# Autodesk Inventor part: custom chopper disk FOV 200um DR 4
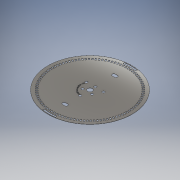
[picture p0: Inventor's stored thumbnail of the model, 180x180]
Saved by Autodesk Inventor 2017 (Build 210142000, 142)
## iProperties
Created: 2016-09
Part Number: custom chopper disk FOV 200um DR 4
Material: Generic
Document SubType Name: Modeling
Designer: Radek
Density: 1 g/cm^3
Appearance: Mirror
Author: Radek
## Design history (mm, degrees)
workplane "Work Plane1"
sketch "Sketch1"
  geometry: L1 (-46.781, 4.422)-(-44.253, 4.183) reference; L2 (-44.362, 2.791)-(-46.897, 2.951) reference; L3 (-46.411, 7.351)-(-43.903, 6.954) reference; L4 (-44.099, 5.571)-(-46.619, 5.889) reference; L5 (-45.858, 10.251)-(-43.38, 9.696) reference; L6 (-43.663, 8.329)-(-46.158, 8.805) reference; L7 (-45.124, 13.11)-(-42.685, 12.401) reference; L8 (-43.054, 11.054)-(-45.514, 11.686) reference; L9 (-44.212, 15.917)-(-41.822, 15.057) reference; L10 (-42.274, 13.736)-(-44.69, 14.521) reference; L11 (-43.125, 18.662)-(-40.794, 17.653) reference; L12 (-41.329, 16.363)-(-43.69, 17.298) reference; L13 (-41.868, 21.333)-(-39.605, 20.18) reference; L14 (-40.22, 18.926)-(-42.518, 20.007) reference; L15 (-40.446, 23.92)-(-38.26, 22.627) reference; L16 (-38.952, 21.414)-(-41.178, 22.638) reference; L17 (-38.865, 26.412)-(-36.764, 24.985) reference; L18 (-37.53, 23.818)-(-39.675, 25.179) reference; L19 (-37.129, 28.801)-(-35.122, 27.244) reference; L20 (-35.961, 26.127)-(-38.016, 27.62) reference; L21 (-35.248, 31.075)-(-33.342, 29.395) reference; L22 (-34.249, 28.333)-(-36.206, 29.953) reference; L23 (-33.227, 33.227)-(-31.431, 31.431) reference; L24 (-32.403, 30.428)-(-34.254, 32.167) reference; L25 (-31.075, 35.248)-(-29.395, 33.342) reference; L26 (-30.428, 32.403)-(-32.167, 34.254) reference; L27 (-28.801, 37.129)-(-27.244, 35.122) reference; L28 (-28.333, 34.249)-(-29.953, 36.206) reference; L29 (-26.412, 38.865)-(-24.985, 36.764) reference; L30 (-26.127, 35.961)-(-27.62, 38.016) reference; L31 (-23.92, 40.446)-(-22.627, 38.26) reference; L32 (-23.818, 37.53)-(-25.179, 39.675) reference; L33 (-21.333, 41.868)-(-20.18, 39.605) reference; L34 (-21.414, 38.952)-(-22.638, 41.178) reference; L35 (-18.662, 43.125)-(-17.653, 40.794) reference; L36 (-18.926, 40.22)-(-20.007, 42.518) reference; L37 (-15.917, 44.212)-(-15.057, 41.822) reference; L38 (-16.363, 41.329)-(-17.298, 43.69) reference; L39 (-13.11, 45.124)-(-12.401, 42.685) reference; L40 (-13.736, 42.274)-(-14.521, 44.69) reference; L41 (-10.251, 45.858)-(-9.696, 43.38) reference; L42 (-11.054, 43.054)-(-11.686, 45.514) reference; L43 (-7.351, 46.411)-(-6.954, 43.903) reference; L44 (-8.329, 43.663)-(-8.805, 46.158) reference; L45 (-4.422, 46.781)-(-4.183, 44.253) reference; L46 (-5.571, 44.099)-(-5.889, 46.619) reference; L47 (-1.476, 46.967)-(-1.396, 44.428) reference; L48 (-2.791, 44.362)-(-2.951, 46.897) reference; L49 (1.476, 46.967)-(1.396, 44.428) reference; L50 (0, 44.45)-(0, 46.99) reference; L51 (4.422, 46.781)-(4.183, 44.253) reference; L52 (2.791, 44.362)-(2.951, 46.897) reference; L53 (7.351, 46.411)-(6.954, 43.903) reference; L54 (5.571, 44.099)-(5.889, 46.619) reference; L55 (10.251, 45.858)-(9.696, 43.38) reference; L56 (8.329, 43.663)-(8.805, 46.158) reference; L57 (13.11, 45.124)-(12.401, 42.685) reference; L58 (11.054, 43.054)-(11.686, 45.514) reference; L59 (15.917, 44.212)-(15.057, 41.822) reference; L60 (13.736, 42.274)-(14.521, 44.69) reference; L61 (18.662, 43.125)-(17.653, 40.794) reference; L62 (16.363, 41.329)-(17.298, 43.69) reference; L63 (21.333, 41.868)-(20.18, 39.605) reference; L64 (18.926, 40.22)-(20.007, 42.518) reference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; C1 r 50.8 at (0, 0) reference; C2 r 2.984 at (0, 0) reference; C3 r 1.524 at (0, 6.553) reference; C4 r 1.524 at (10.339, 5.969) reference; C5 r 2.984 at (0, 0) reference; C6 r 1.524 at (0, -11.938) reference; C7 r 1.524 at (-5.675, -3.277) reference; C8 r 1.524 at (-10.339, 5.969) reference; C9 r 1.524 at (5.675, -3.277) reference; C10 r 50.8 at (0, 0) reference; C11 r 1.524 at (-5.675, -3.277) reference; C12 r 1.524 at (-10.339, 5.969) reference; C13 r 1.524 at (0, 6.553) reference; C14 r 1.524 at (10.339, 5.969) reference; C15 r 1.524 at (5.675, -3.277) reference; C16 r 1.524 at (0, -11.938) reference; C17 r 2.984 at (0, 0) reference; A1 r 17.081 centre (0, 0) between (0, -17.081) and (17.081, 0) reference; A2 r 17.081 centre (0, 0) between (0, 17.081) and (-17.081, 0) reference; A3 r 43.18 centre (0, 0) between (0, 43.18) and (-43.18, 0) reference; A4 r 43.18 centre (0, 0) between (0, -43.18) and (43.18, 0) reference; A5 r 44.45 centre (0, 0) between (-44.253, 4.183) and (-44.362, 2.791) reference; A6 r 46.99 centre (0, 0) between (-46.781, 4.422) and (-46.897, 2.951) reference; A7 r 44.45 centre (0, 0) between (-43.903, 6.954) and (-44.099, 5.571) reference; A8 r 46.99 centre (0, 0) between (-46.411, 7.351) and (-46.619, 5.889) reference; A9 r 44.45 centre (0, 0) between (-43.38, 9.696) and (-43.663, 8.329) reference; A10 r 46.99 centre (0, 0) between (-45.858, 10.251) and (-46.158, 8.805) reference; A11 r 44.45 centre (0, 0) between (-42.685, 12.401) and (-43.054, 11.054) reference; A12 r 46.99 centre (0, 0) between (-45.124, 13.11) and (-45.514, 11.686) reference; A13 r 44.45 centre (0, 0) between (-41.822, 15.057) and (-42.274, 13.736) reference; A14 r 46.99 centre (0, 0) between (-44.212, 15.917) and (-44.69, 14.521) reference; A15 r 44.45 centre (0, 0) between (-40.794, 17.653) and (-41.329, 16.363) reference; A16 r 46.99 centre (0, 0) between (-43.125, 18.662) and (-43.69, 17.298) reference; A17 r 44.45 centre (0, 0) between (-39.605, 20.18) and (-40.22, 18.926) reference; A18 r 46.99 centre (0, 0) between (-41.868, 21.333) and (-42.518, 20.007) reference; A19 r 44.45 centre (0, 0) between (-38.26, 22.627) and (-38.952, 21.414) reference; A20 r 46.99 centre (0, 0) between (-40.446, 23.92) and (-41.178, 22.638) reference; A21 r 44.45 centre (0, 0) between (-36.764, 24.985) and (-37.53, 23.818) reference; A22 r 46.99 centre (0, 0) between (-38.865, 26.412) and (-39.675, 25.179) reference; A23 r 44.45 centre (0, 0) between (-35.122, 27.244) and (-35.961, 26.127) reference; A24 r 46.99 centre (0, 0) between (-37.129, 28.801) and (-38.016, 27.62) reference; A25 r 44.45 centre (0, 0) between (-33.342, 29.395) and (-34.249, 28.333) reference; A26 r 46.99 centre (0, 0) between (-35.248, 31.075) and (-36.206, 29.953) reference; A27 r 44.45 centre (0, 0) between (-31.431, 31.431) and (-32.403, 30.428) reference; A28 r 46.99 centre (0, 0) between (-33.227, 33.227) and (-34.254, 32.167) reference; A29 r 44.45 centre (0, 0) between (-29.395, 33.342) and (-30.428, 32.403) reference; A30 r 46.99 centre (0, 0) between (-31.075, 35.248) and (-32.167, 34.254) reference; A31 r 44.45 centre (0, 0) between (-27.244, 35.122) and (-28.333, 34.249) reference; A32 r 46.99 centre (0, 0) between (-28.801, 37.129) and (-29.953, 36.206) reference; A33 r 44.45 centre (0, 0) between (-24.985, 36.764) and (-26.127, 35.961) reference; A34 r 46.99 centre (0, 0) between (-26.412, 38.865) and (-27.62, 38.016) reference; A35 r 44.45 centre (0, 0) between (-22.627, 38.26) and (-23.818, 37.53) reference; A36 r 46.99 centre (0, 0) between (-23.92, 40.446) and (-25.179, 39.675) reference; A37 r 44.45 centre (0, 0) between (-20.18, 39.605) and (-21.414, 38.952) reference; A38 r 46.99 centre (0, 0) between (-21.333, 41.868) and (-22.638, 41.178) reference; A39 r 44.45 centre (0, 0) between (-17.653, 40.794) and (-18.926, 40.22) reference; A40 r 46.99 centre (0, 0) between (-18.662, 43.125) and (-20.007, 42.518) reference; A41 r 44.45 centre (0, 0) between (-15.057, 41.822) and (-16.363, 41.329) reference; A42 r 46.99 centre (0, 0) between (-15.917, 44.212) and (-17.298, 43.69) reference; A43 r 44.45 centre (0, 0) between (-12.401, 42.685) and (-13.736, 42.274) reference; A44 r 46.99 centre (0, 0) between (-13.11, 45.124) and (-14.521, 44.69) reference; A45 r 44.45 centre (0, 0) between (-9.696, 43.38) and (-11.054, 43.054) reference; A46 r 46.99 centre (0, 0) between (-10.251, 45.858) and (-11.686, 45.514) reference; A47 r 44.45 centre (0, 0) between (-6.954, 43.903) and (-8.329, 43.663) reference; A48 r 46.99 centre (0, 0) between (-7.351, 46.411) and (-8.805, 46.158) reference; A49 r 44.45 centre (0, 0) between (-4.183, 44.253) and (-5.571, 44.099) reference; A50 r 46.99 centre (0, 0) between (-4.422, 46.781) and (-5.889, 46.619) reference; A51 r 44.45 centre (0, 0) between (-1.396, 44.428) and (-2.791, 44.362) reference; A52 r 46.99 centre (0, 0) between (-1.476, 46.967) and (-2.951, 46.897) reference; A53 r 44.45 centre (0, 0) between (1.396, 44.428) and (0, 44.45) reference; A54 r 46.99 centre (0, 0) between (1.476, 46.967) and (0, 46.99) reference; A55 r 44.45 centre (0, 0) between (4.183, 44.253) and (2.791, 44.362) reference; A56 r 46.99 centre (0, 0) between (4.422, 46.781) and (2.951, 46.897) reference; A57 r 44.45 centre (0, 0) between (6.954, 43.903) and (5.571, 44.099) reference; A58 r 46.99 centre (0, 0) between (7.351, 46.411) and (5.889, 46.619) reference; A59 r 44.45 centre (0, 0) between (9.696, 43.38) and (8.329, 43.663) reference; A60 r 46.99 centre (0, 0) between (10.251, 45.858) and (8.805, 46.158) reference; A61 r 44.45 centre (0, 0) between (12.401, 42.685) and (11.054, 43.054) reference; A62 r 46.99 centre (0, 0) between (13.11, 45.124) and (11.686, 45.514) reference; A63 r 44.45 centre (0, 0) between (15.057, 41.822) and (13.736, 42.274) reference; A64 r 46.99 centre (0, 0) between (15.917, 44.212) and (14.521, 44.69) reference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; 1 further point
  constraints: 8 end point, 2 collinear, 1 parallel
extrude "Extrusion2" new body sketch "Sketch1" distance "d2" = 0.254; taper "d3" = 0 deg
sketch "Sketch2"
  geometry: L1 (-46.781, 4.422)-(-44.253, 4.183) reference; L2 (-44.362, 2.791)-(-46.897, 2.951) reference; L3 (-46.411, 7.351)-(-43.903, 6.954) reference; L4 (-44.099, 5.571)-(-46.619, 5.889) reference; L5 (-45.858, 10.251)-(-43.38, 9.696) reference; L6 (-43.663, 8.329)-(-46.158, 8.805) reference; L7 (-45.124, 13.11)-(-42.685, 12.401) reference; L8 (-43.054, 11.054)-(-45.514, 11.686) reference; L9 (-44.212, 15.917)-(-41.822, 15.057) reference; L10 (-42.274, 13.736)-(-44.69, 14.521) reference; L11 (-43.125, 18.662)-(-40.794, 17.653) reference; L12 (-41.329, 16.363)-(-43.69, 17.298) reference; L13 (-41.868, 21.333)-(-39.605, 20.18) reference; L14 (-40.22, 18.926)-(-42.518, 20.007) reference; L15 (-40.446, 23.92)-(-38.26, 22.627) reference; L16 (-38.952, 21.414)-(-41.178, 22.638) reference; L17 (-38.865, 26.412)-(-36.764, 24.985) reference; L18 (-37.53, 23.818)-(-39.675, 25.179) reference; L19 (-37.129, 28.801)-(-35.122, 27.244) reference; L20 (-35.961, 26.127)-(-38.016, 27.62) reference; L21 (-35.248, 31.075)-(-33.342, 29.395) reference; L22 (-34.249, 28.333)-(-36.206, 29.953) reference; L23 (-33.227, 33.227)-(-31.431, 31.431) reference; L24 (-32.403, 30.428)-(-34.254, 32.167) reference; L25 (-31.075, 35.248)-(-29.395, 33.342) reference; L26 (-30.428, 32.403)-(-32.167, 34.254) reference; L27 (-28.801, 37.129)-(-27.244, 35.122) reference; L28 (-28.333, 34.249)-(-29.953, 36.206) reference; L29 (-26.412, 38.865)-(-24.985, 36.764) reference; L30 (-26.127, 35.961)-(-27.62, 38.016) reference; L31 (-23.92, 40.446)-(-22.627, 38.26) reference; L32 (-23.818, 37.53)-(-25.179, 39.675) reference; L33 (-21.333, 41.868)-(-20.18, 39.605) reference; L34 (-21.414, 38.952)-(-22.638, 41.178) reference; L35 (-18.662, 43.125)-(-17.653, 40.794) reference; L36 (-18.926, 40.22)-(-20.007, 42.518) reference; L37 (-15.917, 44.212)-(-15.057, 41.822) reference; L38 (-16.363, 41.329)-(-17.298, 43.69) reference; L39 (-13.11, 45.124)-(-12.401, 42.685) reference; L40 (-13.736, 42.274)-(-14.521, 44.69) reference; L41 (-10.251, 45.858)-(-9.696, 43.38) reference; L42 (-11.054, 43.054)-(-11.686, 45.514) reference; L43 (-7.351, 46.411)-(-6.954, 43.903) reference; L44 (-8.329, 43.663)-(-8.805, 46.158) reference; L45 (-4.422, 46.781)-(-4.183, 44.253) reference; L46 (-5.571, 44.099)-(-5.889, 46.619) reference; L47 (-1.476, 46.967)-(-1.396, 44.428) reference; L48 (-2.791, 44.362)-(-2.951, 46.897) reference; L49 (1.476, 46.967)-(1.396, 44.428) reference; L50 (0, 44.45)-(0, 46.99) reference; L51 (4.422, 46.781)-(4.183, 44.253) reference; L52 (2.791, 44.362)-(2.951, 46.897) reference; L53 (7.351, 46.411)-(6.954, 43.903) reference; L54 (5.571, 44.099)-(5.889, 46.619) reference; L55 (10.251, 45.858)-(9.696, 43.38) reference; L56 (8.329, 43.663)-(8.805, 46.158) reference; L57 (13.11, 45.124)-(12.401, 42.685) reference; L58 (11.054, 43.054)-(11.686, 45.514) reference; L59 (15.917, 44.212)-(15.057, 41.822) reference; L60 (13.736, 42.274)-(14.521, 44.69) reference; L61 (18.662, 43.125)-(17.653, 40.794) reference; L62 (16.363, 41.329)-(17.298, 43.69) reference; L63 (21.333, 41.868)-(20.18, 39.605) reference; L64 (18.926, 40.22)-(20.007, 42.518) reference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; C1 r 50.8 at (0, 0) reference; C2 r 1.524 at (-5.675, -3.277) reference; C3 r 1.524 at (-10.339, 5.969) reference; C4 r 1.524 at (0, 6.553) reference; C5 r 1.524 at (10.339, 5.969) reference; C6 r 1.524 at (5.675, -3.277) reference; C7 r 1.524 at (0, -11.938) reference; C8 r 2.984 at (0, 0) reference; A1 r 44.45 centre (0, 0) between (-44.253, 4.183) and (-44.362, 2.791) reference; A2 r 46.99 centre (0, 0) between (-46.781, 4.422) and (-46.897, 2.951) reference; A3 r 44.45 centre (0, 0) between (-43.903, 6.954) and (-44.099, 5.571) reference; A4 r 46.99 centre (0, 0) between (-46.411, 7.351) and (-46.619, 5.889) reference; A5 r 44.45 centre (0, 0) between (-43.38, 9.696) and (-43.663, 8.329) reference; A6 r 46.99 centre (0, 0) between (-45.858, 10.251) and (-46.158, 8.805) reference; A7 r 44.45 centre (0, 0) between (-42.685, 12.401) and (-43.054, 11.054) reference; A8 r 46.99 centre (0, 0) between (-45.124, 13.11) and (-45.514, 11.686) reference; A9 r 44.45 centre (0, 0) between (-41.822, 15.057) and (-42.274, 13.736) reference; A10 r 46.99 centre (0, 0) between (-44.212, 15.917) and (-44.69, 14.521) reference; A11 r 44.45 centre (0, 0) between (-40.794, 17.653) and (-41.329, 16.363) reference; A12 r 46.99 centre (0, 0) between (-43.125, 18.662) and (-43.69, 17.298) reference; A13 r 44.45 centre (0, 0) between (-39.605, 20.18) and (-40.22, 18.926) reference; A14 r 46.99 centre (0, 0) between (-41.868, 21.333) and (-42.518, 20.007) reference; A15 r 44.45 centre (0, 0) between (-38.26, 22.627) and (-38.952, 21.414) reference; A16 r 46.99 centre (0, 0) between (-40.446, 23.92) and (-41.178, 22.638) reference; A17 r 44.45 centre (0, 0) between (-36.764, 24.985) and (-37.53, 23.818) reference; A18 r 46.99 centre (0, 0) between (-38.865, 26.412) and (-39.675, 25.179) reference; A19 r 44.45 centre (0, 0) between (-35.122, 27.244) and (-35.961, 26.127) reference; A20 r 46.99 centre (0, 0) between (-37.129, 28.801) and (-38.016, 27.62) reference; A21 r 44.45 centre (0, 0) between (-33.342, 29.395) and (-34.249, 28.333) reference; A22 r 46.99 centre (0, 0) between (-35.248, 31.075) and (-36.206, 29.953) reference; A23 r 44.45 centre (0, 0) between (-31.431, 31.431) and (-32.403, 30.428) reference; A24 r 46.99 centre (0, 0) between (-33.227, 33.227) and (-34.254, 32.167) reference; A25 r 44.45 centre (0, 0) between (-29.395, 33.342) and (-30.428, 32.403) reference; A26 r 46.99 centre (0, 0) between (-31.075, 35.248) and (-32.167, 34.254) reference; A27 r 44.45 centre (0, 0) between (-27.244, 35.122) and (-28.333, 34.249) reference; A28 r 46.99 centre (0, 0) between (-28.801, 37.129) and (-29.953, 36.206) reference; A29 r 44.45 centre (0, 0) between (-24.985, 36.764) and (-26.127, 35.961) reference; A30 r 46.99 centre (0, 0) between (-26.412, 38.865) and (-27.62, 38.016) reference; A31 r 44.45 centre (0, 0) between (-22.627, 38.26) and (-23.818, 37.53) reference; A32 r 46.99 centre (0, 0) between (-23.92, 40.446) and (-25.179, 39.675) reference; A33 r 44.45 centre (0, 0) between (-20.18, 39.605) and (-21.414, 38.952) reference; A34 r 46.99 centre (0, 0) between (-21.333, 41.868) and (-22.638, 41.178) reference; A35 r 44.45 centre (0, 0) between (-17.653, 40.794) and (-18.926, 40.22) reference; A36 r 46.99 centre (0, 0) between (-18.662, 43.125) and (-20.007, 42.518) reference; A37 r 44.45 centre (0, 0) between (-15.057, 41.822) and (-16.363, 41.329) reference; A38 r 46.99 centre (0, 0) between (-15.917, 44.212) and (-17.298, 43.69) reference; A39 r 44.45 centre (0, 0) between (-12.401, 42.685) and (-13.736, 42.274) reference; A40 r 46.99 centre (0, 0) between (-13.11, 45.124) and (-14.521, 44.69) reference; A41 r 44.45 centre (0, 0) between (-9.696, 43.38) and (-11.054, 43.054) reference; A42 r 46.99 centre (0, 0) between (-10.251, 45.858) and (-11.686, 45.514) reference; A43 r 44.45 centre (0, 0) between (-6.954, 43.903) and (-8.329, 43.663) reference; A44 r 46.99 centre (0, 0) between (-7.351, 46.411) and (-8.805, 46.158) reference; A45 r 44.45 centre (0, 0) between (-4.183, 44.253) and (-5.571, 44.099) reference; A46 r 46.99 centre (0, 0) between (-4.422, 46.781) and (-5.889, 46.619) reference; A47 r 44.45 centre (0, 0) between (-1.396, 44.428) and (-2.791, 44.362) reference; A48 r 46.99 centre (0, 0) between (-1.476, 46.967) and (-2.951, 46.897) reference; A49 r 44.45 centre (0, 0) between (1.396, 44.428) and (0, 44.45) reference; A50 r 46.99 centre (0, 0) between (1.476, 46.967) and (0, 46.99) reference; A51 r 44.45 centre (0, 0) between (4.183, 44.253) and (2.791, 44.362) reference; A52 r 46.99 centre (0, 0) between (4.422, 46.781) and (2.951, 46.897) reference; A53 r 44.45 centre (0, 0) between (6.954, 43.903) and (5.571, 44.099) reference; A54 r 46.99 centre (0, 0) between (7.351, 46.411) and (5.889, 46.619) reference; A55 r 44.45 centre (0, 0) between (9.696, 43.38) and (8.329, 43.663) reference; A56 r 46.99 centre (0, 0) between (10.251, 45.858) and (8.805, 46.158) reference; A57 r 44.45 centre (0, 0) between (12.401, 42.685) and (11.054, 43.054) reference; A58 r 46.99 centre (0, 0) between (13.11, 45.124) and (11.686, 45.514) reference; A59 r 44.45 centre (0, 0) between (15.057, 41.822) and (13.736, 42.274) reference; A60 r 46.99 centre (0, 0) between (15.917, 44.212) and (14.521, 44.69) reference; A61 r 44.45 centre (0, 0) between (17.653, 40.794) and (16.363, 41.329) reference; A62 r 46.99 centre (0, 0) between (18.662, 43.125) and (17.298, 43.69) reference; A63 r 44.45 centre (0, 0) between (20.18, 39.605) and (18.926, 40.22) reference; A64 r 46.99 centre (0, 0) between (21.333, 41.868) and (20.007, 42.518) reference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; 1 further point
  constraints: 8 end point, 1 collinear
extrude "Extrusion3" cut sketch "Sketch2" stored distance "d4" = 0.254; taper "d5" = 0 deg
sketch "Sketch3" dims "d20" = 1.32222 (= 0.5 x holediameter), "d21" = 1.8699 (= 1.41421 x d20)
  geometry: L1 (-10.339, 5.969)-(10.339, 5.969); L2 (0, 0)-(50.8, 0); L3 (0, 44.45)-(0, 46.99) reference; L4 (0, 0)-(0, 50.8); L5 (0, 30)-(0, 28.13); L6 (0, 50.165)-(0, 48.26) reference; L7 (-48.26, 0)-(-50.165, 0) reference; L8 (0, 0)-(3.805, 36.26); L9 (0, 50.8)-(0, 50.165); L10 (1.698, 28.079)-(1.801, 31.811); L11 (-1.698, 28.079)-(-1.801, 31.811); C1 r 2.984 at (0, 0) reference; C2 r 15.25 at (0, 0); C3 r 1.524 at (-10.339, 5.969) reference; C4 r 1.524 at (0, -11.938) reference; C5 r 1.524 at (10.339, 5.969) reference; C6 r 1.524 at (-5.675, -3.277) reference; C7 r 1.524 at (5.675, -3.277) reference; A1 r 50.8 centre (0, 0) between (50.8, 0) and (0, 50.8) reference; A2 r 48.26 centre (0, 0) between (0, 48.26) and (-48.26, 0) reference; A3 r 50.165 centre (0, 0) between (0, 50.165) and (-50.165, 0) reference; A4 r 50.165 centre (0, 0) between (-20.154, -45.939) and (22.037, -45.066); A5 r 48.26 centre (0, 0) between (-19.033, -44.348) and (20.956, -43.472); 3 further points; 3 other entities
  constraints: 16 end point, 8 point on circle, 3 centre point, 3 coincident, 2 vertical, 1 collinear, 1 horizontal, 1 parallel, 1 point on line, 1 vertical alignment, 19 other
  dimensions: "d9" = 30.5 diameter of C2; "d18" = 0 distance between parallel lines of L4 L5; "d19" = 30 distance of point (0, 0) L5.start (= offaxis); "d24" = 0.60415 dimension on point (0, 0) L5.start point (-1.811, 29.945) (= 0.5 x angle); "d28" = 0.60415 dimension on point (0, 0) point (1.811, 29.945) L5.start (= 0.5 x angle); "d32" = 0.635 distance of L4.end L6.start (derived)
extrude "Extrusion7" cut sketch "Sketch3" stored distance "d40" = 10; taper "d41" = 0 deg
sketch "Sketch4"
  geometry: L1 (-1.801, 31.811)-(-1.698, 28.079) reference; L2 (1.698, 28.079)-(1.801, 31.811) reference; L3 (1.801, 31.811)-(1.698, 28.079) reference; L4 (-1.698, 28.079)-(-1.801, 31.811) reference; L5 (-1.698, 28.079)-(-1.801, 31.811); L6 (1.698, 28.079)-(1.801, 31.811); C1 r 2.984 at (0, 0) reference; C2 r 50.8 at (0, 0) reference; A1 r 28.13 centre (0, 0) between (1.698, 28.079) and (-1.698, 28.079); A2 r 31.862 centre (0, 0) between (1.801, 31.811) and (-1.801, 31.811); 3 further points; 2 other entities
  constraints: 4 end point, 4 point on circle, 2 centre point, 2 coincident, 2 collinear, 2 other
extrude "Extrusion8" cut sketch "Sketch4" stored distance "d42" = 10; taper "d43" = 0 deg
sketch "Sketch5"
  geometry: L1 (0, 0)-(-7.947, 50.175); L2 (0, 0)-(7.947, 50.175); L3 (7.524, 47.508)-(7.837, 49.483); L4 (-7.524, 47.508)-(-7.837, 49.483); L5 (6.954, 43.903)-(7.351, 46.411) reference; L6 (4.422, 46.781)-(4.183, 44.253) reference; L7 (7.351, 46.411)-(6.954, 43.903) reference; C1 r 2.984 at (0, 0) reference; A1 r 50.8 centre (0, 0) between (-7.947, 50.175) and (7.947, 50.175) reference; A2 r 28.13 centre (0, 0) between (1.698, 28.079) and (-1.698, 28.079) reference; A3 r 31.862 centre (0, 0) between (1.801, 31.811) and (-1.801, 31.811) reference; A4 r 48.1 centre (0, 0) between (7.524, 47.508) and (-7.524, 47.508); A5 r 50.1 centre (0, 0) between (7.837, 49.483) and (-7.837, 49.483); 4 further points; 2 other entities
  constraints: 8 end point, 6 point on circle, 3 point on line, 2 centre point, 2 coincident, 2 collinear, 1 midpoint, 8 other
  dimensions: "d44" = 0.7 radial gap between concentric circles of A1 A5; "d45" = 2 radial gap between concentric circles of A5 A4; "d53" = 18 deg angle of L1 L2
extrude "Extrusion9" cut sketch "Sketch5" stored distance "d46" = 10; taper "d47" = 0 deg
pattern_circular "Circular Pattern3" dims angle "d49" = 360 deg
sketch "Sketch6"
  geometry: L1 (28.13, 0)-(28.079, 0) reference; L2 (31.811, 0)-(31.862, 0) reference; L3 (28.079, -0.254)-(28.13, -0.254) reference; L4 (31.862, -0.254)-(31.811, -0.254) reference; L5 (-50.8, 0)-(50.8, 0) reference; L6 (-50.8, -0.254)-(50.8, -0.254) reference; L7 (28.13, 0)-(31.862, 0); L8 (28.13, -0.254)-(31.862, -0.254); L9 (29.996, -0.254)-(29.996, 0); L10 (29.996, -0.127)-(32.931, -3.062); 1 further point
  constraints: 8 end point, 3 midpoint, 1 collinear, 1 parallel
  dimensions: "d51" = 135 deg angle of L10 L9
workaxis "Work Axis1"
workplane "Work Plane3"
  workplane "Work Plane2"
sketch "Sketch7"
  geometry: L1 (0, -11.938)-(-10.339, 5.969); C1 r 1.524 at (0, -11.938) reference; C2 r 1.524 at (-10.339, 5.969) reference; C3 r 2.984 at (0, 0) reference; C4 r 10.414 at (0, 0); 2 further points
  constraints: 2 end point, 1 centre point, 1 coincident, 1 tangent, 1 other
extrude "Extrusion11" cut sketch "Sketch7" stored distance "d57" = 10; taper "d58" = 0 deg
body "Solid2"
pattern_circular "Circular Pattern1" dims angle "d7" = 360 deg
node "Reference1"
node "Reference2"
node "Reference3"
node "Reference4"
node "Reference5"
node "Reference6"
node "Reference7"
node "Reference8"
node "Reference9"
node "Reference10"
node "Reference11"
node "Reference12"
node "Reference13"
node "Reference14"
node "Reference15"
node "Reference16"
node "Reference17"
node "Reference18"
node "Reference19"
other parameters: "d12" = 1.72222 (computed from ftube, FOV), "FOV" = 0.2 [user parameter; used in 2 equation terms], "dutycycle" = 0.6652 (computed from holelength, offaxis) [user parameter], "offaxis" = 30 [user parameter; used in 4 equation terms], "angle" = 1.2083 (computed from holediameter, holelength, offaxis) [user parameter; used in 2 equation terms], "holelength" = 6.26936 (computed from dutyratio, offaxis, holediameter) [user parameter; used in 2 equation terms], "holediameter" = 2.64444 (computed from FOV, ftube) [user parameter; used in 3 equation terms], "dutyratio" = 0.4 [user parameter; used in 1 equation term], "d52" = 45 deg
